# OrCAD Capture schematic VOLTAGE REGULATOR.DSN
size A
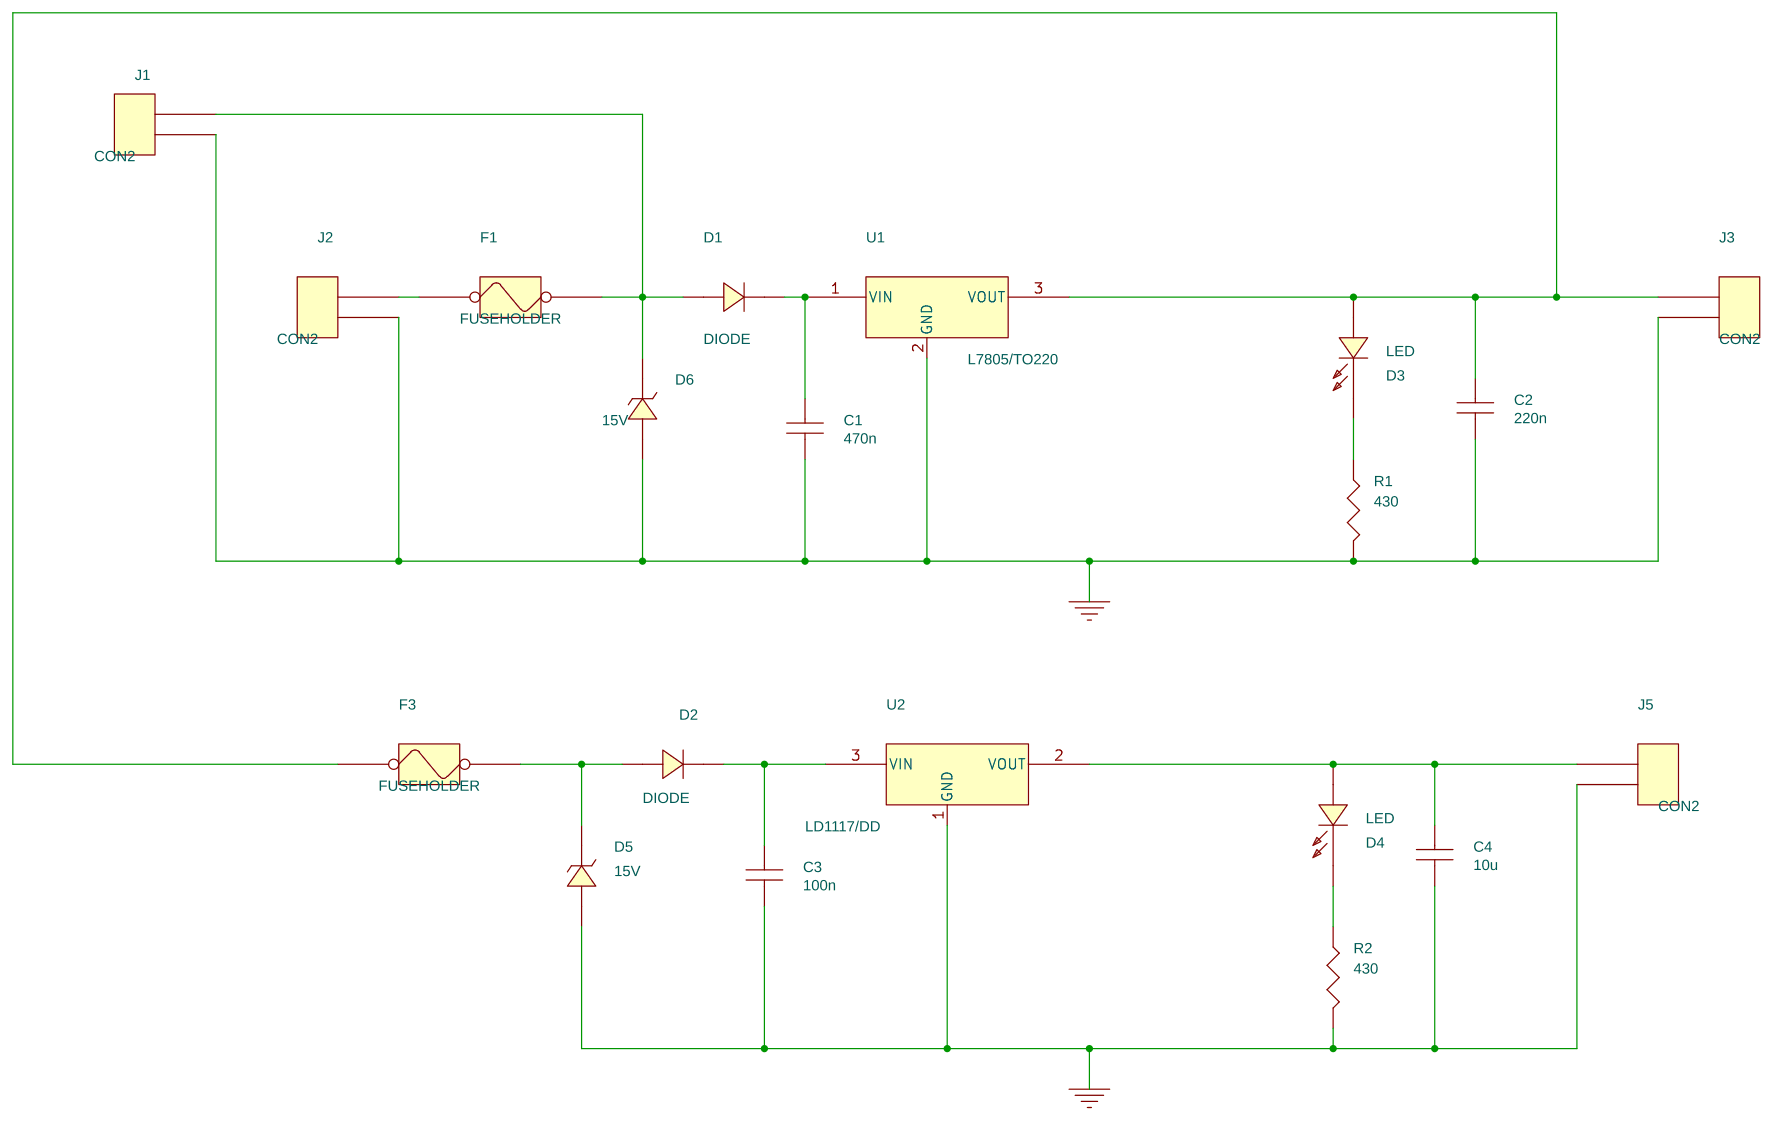
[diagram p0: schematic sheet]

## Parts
C1  470n  [GU-RC200]
C2  220n  [GU-RC200]
C3  100n  [GU-RC200]
C4  10u  [GU-RC200]
D1  DIODE  [GU-1N4001]
D2  DIODE  [GU-1N4001]
D3  LED  [GU-led5mm]
D4  LED  [GU-led5mm]
D5  15V  [GU-1N4001]
D6  15V  [GU-1N4001]
F1  FUSEHOLDER  [GU-Fuseholder-20mm]
F3  FUSEHOLDER  [GU-Fuseholder-20mm]
J1  CON2  [GU-terminal2-200]
J2  CON2  [GU-terminal2-200]
J3  CON2  [GU-terminal2-200]
J5  CON2  [GU-terminal2-200]
R1  430  [GU-RC400]
R2  430  [GU-RC400]
U1  L7805/TO220  [GU-TO220AB-HSINK]
U2  LD1117/DD  [GU-TO220AB-HSINK]

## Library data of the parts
C1-C4 = CAP_NP
D1 D2 = DIODE
D3 D4 = LED
D5 D6 = DIODE_ZENER
F1 F3 = FUSEHOLDER
J1-J3 J5 = CON2
R1 R2 = R
U1 = L7805_TO220_1
U2 = LD1117_DD_0

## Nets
GND: C1.2 C2.2 C3.2 C4.2 D5.2(ANODE) D6.2(ANODE) J1.2 J2.2 J3.2 J5.2 R1.2 R2.2 U1.2(GND) U2.1(GND)
N00482: F1.1 J2.1
N00486: D1.2(A) D6.1(CATHODE) F1.2 J1.1
N00778: C2.1 D3.2(ANODE) F3.1 J3.1 U1.3(VOUT)
N01243: C1.1 D1.1(K) U1.1(VIN)
N01262: D3.1(CATHODE) R1.1
N01283: D2.2(A) D5.1(CATHODE) F3.2
N01420: C3.1 D2.1(K) U2.3(VIN)
N01440: C4.1 D4.2(ANODE) J5.1 U2.2(VOUT)
N01448: D4.1(CATHODE) R2.1
